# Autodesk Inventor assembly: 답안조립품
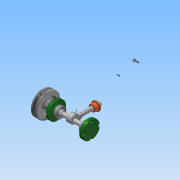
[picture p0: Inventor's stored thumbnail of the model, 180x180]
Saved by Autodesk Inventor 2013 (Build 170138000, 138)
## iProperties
Created: 2016-02
Part Number: 답안조립품
Document SubType Name: Assembly
Designer: Administrator
Author: Administrator
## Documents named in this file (16)
- C:\Users\Administrator\Desktop\460212V1021\답안조립품.iam
- C:\Users\Administrator\Desktop\460212V1021\답안도면.ipt
- C:\Users\Administrator\Desktop\460212V1021\V벨트풀리.ipt
- C:\Users\Administrator\Desktop\460212V1021\고정핀 1.2 x 10.ipt
- C:\Users\Administrator\Desktop\460212V1021\뒤커버.ipt
- C:\Users\Administrator\Desktop\460212V1021\링크.ipt
- C:\Users\Administrator\Desktop\460212V1021\멈춤나사 M3x8.ipt
- C:\Users\Administrator\Desktop\460212V1021\베어링 12 x 32 x 10.ipt
- C:\Users\Administrator\Desktop\460212V1021\볼트 M4 x 12.ipt
- C:\Users\Administrator\Desktop\460212V1021\부시.ipt
- C:\Users\Administrator\Desktop\460212V1021\슬라이드.ipt
- C:\Users\Administrator\Desktop\460212V1021\앞커버.ipt
- C:\Users\Administrator\Desktop\460212V1021\오일실 12 25 7.ipt
- C:\Users\Administrator\Desktop\460212V1021\키 4 x 4 x 10.ipt
- C:\Users\Administrator\Desktop\460212V1021\편심축.ipt
- C:\Users\Administrator\Desktop\460212V1021\핀 5 x 18.ipt
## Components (4 placed, 4 different names)
1. V벨트풀리:1
2. 고정핀 1.2 x 10:1
3. ISO 4762 M4 x 12:1
4. 핀 5 x 18:1
